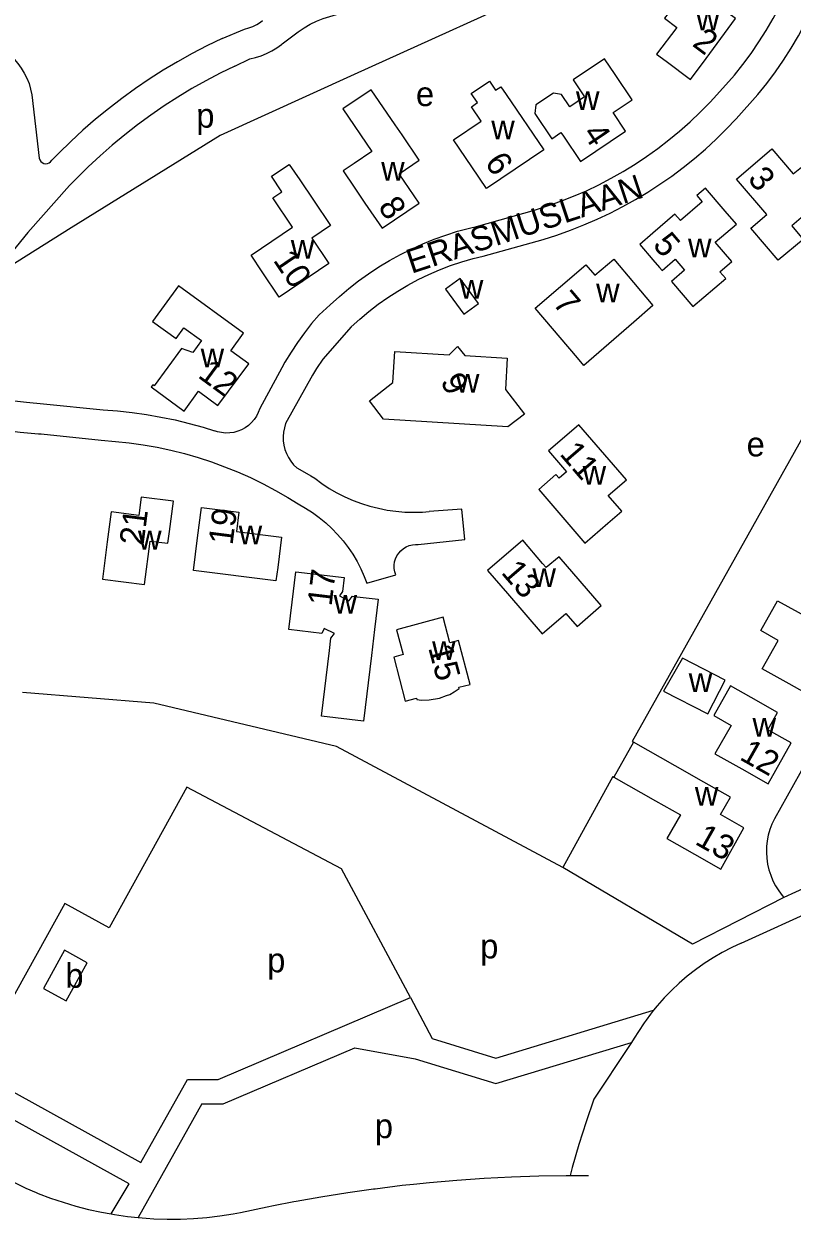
# Model space of a CAD drawing. Extents: x 162804 to 165059, y 381530 to 382901.
# Drawn here: x 163445.8 to 163571.9, y 381530.5 to 381726.8 of the extents above; entities that cross this region are included whole.
import ezdxf

# ---------------------------------------------------------------- set-up
doc = ezdxf.new("R2010")
doc.units = 0
for name, color, linetype in [('BLT_Basislijn', 7, 'Continuous'), ('BLT_Bebouwing', 7, 'Continuous'), ('BLT_Centroide', 7, 'Continuous'), ('BLT_Huisnummer', 7, 'Continuous'), ('BLT_Straatnaam_verkleind', 7, 'Continuous')]:
    doc.layers.add(name, color=color, linetype=linetype)

msp = doc.modelspace()

# ---------------------------------------------------------------- linework, layer by layer
at = {"layer": 'BLT_Basislijn'}
for p, q in [((163478.31, 381724.44), (163481.99, 381725.98)), ((163488.17, 381723.54), (163489.92, 381724.84)), ((163480.43, 381719.91), (163482.9, 381721.07)), ((163559.06, 381714.63), (163562.45, 381718.4)), ((163447.1, 381715.16), (163448.31, 381704.75)), ((163566.31, 381715.22), (163562.74, 381711.25)), ((163600.64, 381707.23), (163545.68, 381608.91)), ((163520.08, 381693.56), (163529.61, 381696.23)), ((163521.2, 381688.68), (163531.02, 381691.43)), ((163496.08, 381680.67), (163494.27, 381679.03)), ((163499.52, 381677.04), (163494.85, 381671.73)), ((163488.12, 381670.33), (163484.5, 381663.62)), ((163493.16, 381669.09), (163488.76, 381661.17)), ((163449.01, 381664.43), (163458.77, 381663.4)), ((163605.92, 381662.34), (163569.01, 381596.23)), ((163448.63, 381659.45), (163458.49, 381658.41)), ((163490.7, 381653.81), (163492.91, 381652.57)), ((163492.91, 381652.57), (163493.53, 381652.17)), ((163502.08, 381634.93), (163506.83, 381636.3)), ((163467.14, 381615.2), (163445.57, 381617)), ((163545.68, 381608.91), (163545.87, 381608.81)), ((163542.48, 381603.17), (163534.27, 381588.25)), ((163542.48, 381603.17), (163542.63, 381603.09)), ((163472.51, 381601.42), (163459.77, 381578.31)), ((163497.94, 381588), (163472.51, 381601.42)), ((163582.56, 381588.85), (163570.59, 381583.31)), ((163509.28, 381566.86), (163497.94, 381588)), ((163563.58, 381575.79), (163584.37, 381585.28)), ((163452.51, 381582.3), (163437.36, 381555.04)), ((163459.77, 381578.31), (163452.51, 381582.3)), ((163477.67, 381553.41), (163509.28, 381566.86)), ((163545.1, 381558.81), (163539.35, 381550.18)), ((163545.56, 381559.5), (163545.1, 381558.81)), ((163546.01, 381560.18), (163545.56, 381559.5)), ((163478.49, 381549.41), (163500.1, 381558.61)), ((163437.36, 381555.04), (163464.99, 381539.75)), ((163464.99, 381539.75), (163472.63, 381553.41)), ((163472.63, 381553.41), (163477.67, 381553.41)), ((163474.98, 381549.41), (163464.53, 381530.72)), ((163474.98, 381549.41), (163478.49, 381549.41))]:
    msp.add_line(p, q, dxfattribs=at)
for points in [[(163538.27, 381743.42), (163534.12, 381734.01), (163500, 381718.5), (163478.02, 381708.51), (163453.55, 381693.34), (163440.16, 381684.96)], [(163562.45, 381718.4), (163563.86, 381720.17), (163565.2, 381721.99), (163566.48, 381723.86), (163567.69, 381725.77), (163568.83, 381727.72), (163569.9, 381729.71), (163570.52, 381730.95)], [(163489.92, 381724.84), (163490.83, 381725.55), (163491.79, 381726.19), (163492.79, 381726.77), (163493.83, 381727.28), (163494.9, 381727.71), (163496, 381728.07), (163497.12, 381728.35), (163498.26, 381728.56), (163499.41, 381728.68), (163499.97, 381728.71)], [(163566.31, 381715.22), (163567.77, 381717.06), (163569.17, 381718.95), (163570.5, 381720.88), (163571.77, 381722.86), (163572.96, 381724.88), (163574.09, 381726.93), (163575.02, 381728.75)], [(163481.99, 381725.98), (163482.69, 381726.16), (163483.37, 381726.4), (163484.01, 381726.72), (163484.62, 381727.11), (163484.97, 381727.38)], [(163478.31, 381724.44), (163475.84, 381723.24), (163473.41, 381721.97), (163471.02, 381720.62), (163468.66, 381719.21), (163466.35, 381717.73), (163464.08, 381716.19), (163461.86, 381714.58), (163459.68, 381712.9), (163457.56, 381711.16), (163455.48, 381709.36), (163453.46, 381707.5), (163451.5, 381705.58), (163450.36, 381704.42)], [(163440.28, 381723.65), (163441.14, 381723.26), (163441.96, 381722.79), (163442.75, 381722.26), (163443.48, 381721.67), (163444.16, 381721.01), (163444.79, 381720.3), (163445.35, 381719.54), (163445.84, 381718.74), (163446.27, 381717.89), (163446.62, 381717.02), (163446.89, 381716.11), (163447.1, 381715.16)], [(163482.9, 381721.07), (163483.83, 381721.28), (163484.75, 381721.57), (163485.63, 381721.94), (163486.49, 381722.38), (163487.3, 381722.88), (163488.07, 381723.46), (163488.17, 381723.54)], [(163480.43, 381719.91), (163478.03, 381718.74), (163475.67, 381717.5), (163473.34, 381716.19), (163471.05, 381714.81), (163468.8, 381713.36), (163466.6, 381711.85), (163464.45, 381710.27), (163462.34, 381708.62), (163460.29, 381706.92), (163458.28, 381705.15), (163456.33, 381703.33), (163454.43, 381701.44), (163453.29, 381700.25)], [(163529.61, 381696.23), (163531.78, 381696.91), (163533.93, 381697.68), (163536.05, 381698.51), (163538.14, 381699.42), (163540.2, 381700.41), (163542.22, 381701.46), (163544.2, 381702.59), (163546.14, 381703.78), (163548.04, 381705.04), (163549.9, 381706.37), (163551.7, 381707.76), (163553.46, 381709.21), (163555.16, 381710.73), (163556.81, 381712.3), (163558.41, 381713.93), (163559.06, 381714.63)], [(163531.02, 381691.43), (163533.28, 381692.14), (163535.51, 381692.93), (163537.72, 381693.79), (163539.89, 381694.73), (163542.03, 381695.73), (163544.14, 381696.81), (163546.2, 381697.96), (163548.23, 381699.18), (163550.22, 381700.47), (163552.16, 381701.83), (163554.05, 381703.24), (163555.89, 381704.73), (163557.69, 381706.27), (163559.43, 381707.87), (163561.11, 381709.53), (163562.74, 381711.25)], [(163448.31, 381704.75), (163448.4, 381704.47), (163448.57, 381704.22), (163448.8, 381704.03), (163449.07, 381703.91), (163449.36, 381703.86), (163449.66, 381703.89), (163449.94, 381704), (163450.17, 381704.18), (163450.36, 381704.42)], [(163453.29, 381700.25), (163446.44, 381692.54), (163440.16, 381684.96)], [(163496.08, 381680.67), (163497.58, 381682.04), (163499.13, 381683.35), (163500.73, 381684.6), (163502.39, 381685.78), (163504.08, 381686.9), (163505.82, 381687.95), (163507.6, 381688.93), (163509.42, 381689.84), (163511.27, 381690.68), (163513.15, 381691.45), (163515.07, 381692.14), (163517, 381692.75), (163518.96, 381693.29), (163520.08, 381693.56)], [(163499.52, 381677.04), (163500.95, 381678.34), (163502.43, 381679.58), (163503.96, 381680.76), (163505.54, 381681.88), (163507.16, 381682.93), (163508.82, 381683.9), (163510.53, 381684.81), (163512.27, 381685.65), (163514.04, 381686.42), (163515.84, 381687.11), (163517.67, 381687.73), (163519.53, 381688.27), (163521.2, 381688.68)], [(163494.27, 381679.03), (163493.02, 381677.58), (163491.83, 381676.07), (163490.7, 381674.51), (163489.64, 381672.91), (163488.65, 381671.27), (163488.12, 381670.33)], [(163494.85, 381671.73), (163493.85, 381670.21), (163493.16, 381669.09)], [(163438.41, 381665.78), (163440.36, 381665.45), (163443.27, 381665.03), (163446.18, 381664.69), (163449.01, 381664.43)], [(163458.77, 381663.4), (163461.16, 381663.23), (163463.54, 381662.98), (163465.91, 381662.65), (163468.27, 381662.24), (163470.61, 381661.76), (163472.94, 381661.19), (163475.24, 381660.55), (163477.07, 381659.98)], [(163484.5, 381663.62), (163484.27, 381662.99), (163483.97, 381662.39), (163483.59, 381661.83), (163483.15, 381661.32), (163482.66, 381660.87), (163482.11, 381660.48), (163481.52, 381660.15), (163480.9, 381659.9), (163480.25, 381659.72), (163479.59, 381659.62), (163478.91, 381659.61), (163478.24, 381659.67), (163477.59, 381659.81), (163477.07, 381659.98)], [(163488.76, 381661.17), (163488.55, 381660.48), (163488.4, 381659.77), (163488.34, 381659.04), (163488.36, 381658.32), (163488.46, 381657.6), (163488.64, 381656.9), (163488.89, 381656.22), (163489.22, 381655.57), (163489.61, 381654.97), (163490.07, 381654.41), (163490.59, 381653.9), (163490.7, 381653.81)], [(163438.36, 381660.72), (163439.24, 381660.56), (163442.21, 381660.12), (163445.19, 381659.77), (163448.18, 381659.48), (163448.63, 381659.45)], [(163458.49, 381658.41), (163460.8, 381658.24), (163463.09, 381658), (163465.38, 381657.67), (163467.65, 381657.27), (163469.91, 381656.79), (163472.15, 381656.23), (163474.37, 381655.59), (163476.57, 381654.87), (163478.74, 381654.08), (163480.88, 381653.22), (163482.99, 381652.28), (163485.06, 381651.27), (163487.1, 381650.18), (163489.1, 381649.03), (163490.83, 381647.96)], [(163493.53, 381652.17), (163494.71, 381651.31), (163495.93, 381650.51), (163497.19, 381649.78), (163498.49, 381649.12), (163499.83, 381648.54), (163501.19, 381648.03), (163502.59, 381647.59), (163504, 381647.24), (163505.43, 381646.96), (163506.87, 381646.75), (163508.33, 381646.63), (163509.78, 381646.59), (163511.24, 381646.63), (163512.31, 381646.71)], [(163490.83, 381647.96), (163492.03, 381647.29), (163493.18, 381646.55), (163494.29, 381645.74), (163495.35, 381644.87), (163496.35, 381643.94), (163497.3, 381642.95), (163498.19, 381641.91), (163499.02, 381640.82), (163499.79, 381639.68), (163500.48, 381638.5), (163501.11, 381637.28), (163501.66, 381636.03), (163502.08, 381634.93)], [(163510.51, 381641.28), (163518.17, 381642.09), (163517.69, 381647.08), (163512.31, 381646.71)], [(163506.83, 381636.3), (163506.67, 381636.82), (163506.58, 381637.35), (163506.57, 381637.89), (163506.64, 381638.42), (163506.8, 381638.94), (163507.02, 381639.43), (163507.32, 381639.88), (163507.67, 381640.28), (163508.09, 381640.62), (163508.55, 381640.9), (163509.05, 381641.11), (163509.57, 381641.24), (163510.1, 381641.3), (163510.51, 381641.28)], [(163534.27, 381588.25), (163497.12, 381608.13), (163467.14, 381615.2)], [(163569.01, 381596.23), (163568.6, 381595.37), (163568.27, 381594.47), (163568.01, 381593.55), (163567.83, 381592.61), (163567.73, 381591.65), (163567.7, 381590.7), (163567.76, 381589.74), (163567.9, 381588.79), (163568.12, 381587.86), (163568.41, 381586.95), (163568.78, 381586.06), (163569.22, 381585.21), (163569.73, 381584.4), (163570.3, 381583.64), (163570.59, 381583.31)], [(163570.59, 381583.31), (163555.58, 381575.61), (163534.27, 381588.25)], [(163563.58, 381575.79), (163562, 381575.06), (163560.45, 381574.26), (163558.95, 381573.38), (163557.49, 381572.44), (163556.07, 381571.44), (163554.7, 381570.36), (163553.38, 381569.23), (163552.11, 381568.04), (163550.9, 381566.79), (163549.75, 381565.49), (163549.19, 381564.79)], [(163509.28, 381566.86), (163512.8, 381560.13), (163523.27, 381556.91), (163549.19, 381564.79)], [(163549.19, 381564.79), (163548.66, 381564.13), (163547.95, 381563.15)], [(163547.95, 381563.15), (163547.64, 381562.73), (163546.68, 381561.28), (163546.01, 381560.18)], [(163500.1, 381558.61), (163510.03, 381556.8), (163523.26, 381552.73), (163545.56, 381559.5)], [(163460.11, 381531.31), (163463.06, 381536.25), (163428.6, 381555.31)], [(163539.35, 381550.18), (163538.1, 381546.46), (163536.93, 381542.72), (163535.83, 381538.96), (163535.46, 381537.62)], [(163509.76, 381536.2), (163512.38, 381536.48), (163516.86, 381536.87), (163521.34, 381537.18), (163525.83, 381537.4), (163530.32, 381537.55), (163534.82, 381537.62), (163535.46, 381537.62)], [(163535.46, 381537.62), (163538.49, 381537.61)], [(163443.49, 381536.83), (163446.12, 381535.53), (163447.77, 381534.83)], [(163490.46, 381533.4), (163494.55, 381534.13), (163498.99, 381534.84), (163503.18, 381535.43)], [(163503.18, 381535.43), (163503.44, 381535.46), (163507.9, 381536.01), (163509.76, 381536.2)], [(163447.77, 381534.83), (163448.12, 381534.68), (163450.15, 381533.91), (163452.21, 381533.22), (163454.3, 381532.6), (163456.4, 381532.06), (163458.52, 381531.59), (163460.11, 381531.31)], [(163486.76, 381532.69), (163490.12, 381533.35), (163490.46, 381533.4)], [(163460.11, 381531.31), (163460.66, 381531.21), (163462.81, 381530.9), (163464.53, 381530.72)], [(163464.53, 381530.72), (163465.85, 381530.62), (163467.14, 381530.53), (163469.31, 381530.46), (163471.48, 381530.47), (163473.65, 381530.57), (163475.82, 381530.74), (163477.98, 381530.99), (163480.13, 381531.32), (163481.32, 381531.54)], [(163481.32, 381531.54), (163485.71, 381532.48), (163486.76, 381532.69)]]:
    msp.add_lwpolyline(points, dxfattribs=at)
at = {"layer": 'BLT_Bebouwing'}
for p, q in [((163524.98, 381715.24), (163531.14, 381706.15)), ((163452.46, 381574.62), (163449, 381568.37))]:
    msp.add_line(p, q, dxfattribs=at)
for points in [[(163557.79, 381721.13), (163562.64, 381727.71), (163555.14, 381733.31), (163552.15, 381729.31), (163550.98, 381727.75), (163552.97, 381726.26), (163549.68, 381721.86), (163551.23, 381720.7), (163555.23, 381717.7), (163557.79, 381721.13)], [(163542.87, 381718.51), (163541.13, 381721.1), (163535.99, 381717.65), (163537.86, 381714.87), (163535.41, 381713.22), (163534.07, 381715.21), (163532.75, 381715.47), (163529.86, 381713.53), (163529.67, 381712.11), (163532.46, 381707.96), (163533.96, 381708.97), (163534.37, 381708.36), (163537.16, 381704.21), (163544.59, 381709.2), (163542.53, 381712.26), (163545.67, 381714.36), (163542.87, 381718.51)], [(163501.79, 381697.39), (163504.59, 381693.24), (163510.66, 381697.36), (163507.38, 381702.2), (163510.67, 381704.44), (163507.87, 381708.58), (163506.73, 381710.26), (163502.82, 381716.02), (163498.17, 381712.86), (163502.91, 381705.88), (163500, 381703.9), (163498.21, 381702.68), (163500, 381700.03), (163501.79, 381697.39)], [(163531.14, 381706.15), (163521.74, 381699.78), (163519.31, 381703.36), (163516.33, 381707.76), (163520.87, 381710.84), (163519.26, 381713.22), (163520.27, 381713.9), (163519.25, 381715.41), (163522.22, 381717.42), (163523.24, 381715.92), (163524.12, 381716.51), (163524.98, 381715.24)], [(163578.11, 381700.63), (163580.09, 381698.34), (163575.34, 381694.27), (163574.18, 381695.63), (163571.87, 381693.64), (163573.76, 381691.43), (163569.63, 381688.03), (163565.16, 381693.25), (163567.78, 381695.49), (163562.79, 381701.3), (163568.6, 381706.28), (163572.12, 381702.17), (163574.84, 381704.41), (163578.11, 381700.63)], [(163493.35, 381697.85), (163496.14, 381693.7), (163493.04, 381691.61), (163495.85, 381687.44), (163487.71, 381681.95), (163484.92, 381686.1), (163483.08, 381688.82), (163489.9, 381693.42), (163486.66, 381698.23), (163488.16, 381699.25), (163486.45, 381701.8), (163489.33, 381703.74), (163491.08, 381701.21), (163493.35, 381697.85)], [(163550.15, 381686.79), (163550.56, 381686.32), (163552.71, 381688.17), (163554.26, 381686.37), (163552.11, 381684.52), (163555.64, 381680.4), (163561.02, 381685.02), (163560.07, 381686.12), (163562.02, 381687.8), (163559.31, 381690.94), (163562.77, 381693.91), (163560.94, 381696.04), (163557.68, 381699.84), (163556.27, 381698.63), (163557.16, 381697.59), (163553.58, 381694.51), (163552.68, 381695.55), (163549.08, 381692.47), (163546.9, 381690.59), (163549.08, 381688.04), (163550.15, 381686.79)], [(163538.07, 381687.27), (163539.55, 381685.53), (163542.63, 381688.15), (163545.87, 381684.35), (163549.08, 381680.58), (163545.93, 381677.82), (163537.75, 381670.73), (163536.71, 381671.94), (163529.71, 381680.14), (163538.07, 381687.27)], [(163471.14, 381683.79), (163466.9, 381677.96), (163470.76, 381675.15), (163472.03, 381676.89), (163474.93, 381674.79), (163473.53, 381672.84), (163471.67, 381673.48), (163467.18, 381667.37), (163466.93, 381667.55), (163466.66, 381667.18), (163472.07, 381663.2), (163474.47, 381666.47), (163477.63, 381664.15), (163482.71, 381670.97), (163479.74, 381673.13), (163481.83, 381676.01), (163471.14, 381683.79)], [(163541.67, 381644.8), (163543.96, 381646.77), (163541.74, 381649.36), (163544.71, 381651.92), (163536.93, 381660.97), (163535.71, 381659.92), (163531.92, 381656.66), (163534.88, 381653.21), (163533.66, 381652.17), (163533.14, 381652.78), (163530.31, 381650.34), (163537.88, 381641.54), (163541.67, 381644.8)], [(163469.7, 381643.44), (163470.33, 381648.39), (163465.04, 381649.07), (163464.66, 381646.08), (163460.11, 381646.66), (163459.47, 381641.71), (163458.68, 381635.59), (163465.57, 381634.7), (163466.49, 381641.86), (163469.44, 381641.49), (163469.7, 381643.44)], [(163487.45, 381637.53), (163487.17, 381635.31), (163473.61, 381637.05), (163474.3, 381642.41), (163474.94, 381647.37), (163481.09, 381646.58), (163480.69, 381643.44), (163488.09, 381642.49), (163487.45, 381637.53)], [(163530.96, 381638.2), (163527.7, 381641.99), (163521.92, 381637.02), (163525.18, 381633.23), (163530.87, 381626.6), (163534.79, 381629.97), (163536.61, 381627.84), (163540.57, 381631.25), (163533.65, 381639.29), (163531.56, 381637.49), (163530.96, 381638.2)], [(163500, 381632.77), (163503.95, 381632.31), (163503.36, 381627.35), (163502.85, 381623.07), (163501.55, 381612.27), (163494.67, 381613.09), (163495.95, 381623.89), (163496.19, 381625.89), (163496.77, 381626.67), (163495.08, 381627.5), (163494.72, 381626.67), (163489.28, 381627.32), (163489.82, 381631.83), (163490.41, 381636.79), (163498.39, 381635.85), (163498.12, 381633.6), (163497.58, 381632.87), (163499.16, 381632.02), (163499.74, 381632.8), (163500, 381632.77)], [(163572.94, 381630.16), (163577.3, 381627.72), (163575.7, 381624.86), (163579.57, 381622.69), (163575.83, 381615.95), (163571.46, 381618.38), (163567.02, 381620.86), (163569.64, 381625.54), (163566.78, 381627.14), (163569.53, 381632.06), (163572.94, 381630.16)], [(163514.6, 381629.34), (163506.98, 381627.29), (163508.08, 381623.2), (163506.55, 381622.8), (163508.4, 381615.58), (163510.24, 381616.05), (163510.29, 381615.85), (163511.08, 381615.71), (163512.35, 381615.77), (163514.04, 381616.06), (163515.17, 381616.46), (163515.72, 381616.65), (163516.41, 381617.08), (163517.27, 381617.64), (163517.22, 381617.83), (163519.06, 381618.3), (163517.12, 381625.53), (163515.73, 381625.15), (163514.6, 381629.34)], [(163565.19, 381616.15), (163561.83, 381618.06), (163559.07, 381613.18), (163561.9, 381611.58), (163559.26, 381606.91), (163563.65, 381604.42), (163568, 381601.96), (163571.77, 381608.69), (163567.94, 381610.86), (163569.55, 381613.69), (163565.19, 381616.15)], [(163545.87, 381608.81), (163542.63, 381603.09)], [(163552.74, 381604.92), (163545.87, 381608.81)], [(163557.44, 381602.26), (163552.74, 381604.92)], [(163542.63, 381603.09), (163549.51, 381599.2)], [(163549.51, 381599.2), (163553.6, 381596.88), (163551.38, 381592.97), (163555.87, 381590.43), (163560.23, 381587.97), (163563.99, 381594.77), (163560.16, 381596.93), (163561.79, 381599.8), (163557.44, 381602.26)], [(163449, 381568.37), (163452.72, 381566.31), (163456.18, 381572.57), (163452.46, 381574.62)]]:
    msp.add_lwpolyline(points, dxfattribs=at)
for points in [[(163517.43, 381685.02), (163515.03, 381683.27), (163518.03, 381679.15), (163520.43, 381680.9)], [(163506.7, 381673.03), (163515.63, 381672.48), (163516.99, 381673.85), (163518.18, 381672.32), (163525.16, 381671.89), (163524.85, 381666.75), (163527.97, 381662.72), (163525.26, 381660.61), (163504.85, 381661.87), (163502.51, 381664.88), (163506.38, 381667.89)], [(163553.91, 381622.61), (163550.81, 381617.19), (163558.08, 381613.45), (163560.93, 381618.99)]]:
    msp.add_lwpolyline(points, close=True, dxfattribs=at)

# ---------------------------------------------------------------- texts
at = {"layer": 'BLT_Centroide'}
for s, p in [('w', (163556.16, 381725.75)), ('e', (163510.16, 381713.32)), ('w', (163536.43, 381712.66)), ('p', (163474.09, 381709.78)), ('w', (163522.52, 381707.88)), ('w', (163504.44, 381701.09)), ('w', (163489.61, 381688.23)), ('w', (163554.83, 381688.47)), ('w', (163517.36, 381681.67)), ('w', (163539.74, 381681.09)), ('w', (163474.8, 381670.42)), ('w', (163516.72, 381666.25)), ('e', (163564.46, 381655.77)), ('w', (163537.52, 381651.12)), ('w', (163464.52, 381640.47)), ('w', (163481.05, 381641.34)), ('w', (163529.28, 381634.3)), ('w', (163496.63, 381629.94)), ('w', (163512.8, 381622.34)), ('w', (163554.95, 381617.04)), ('w', (163565.42, 381609.72)), ('w', (163555.96, 381598.38)), ('p', (163520.71, 381573.29)), ('b', (163452.59, 381568.47)), ('p', (163485.73, 381571.01)), ('p', (163503.41, 381543.76))]:
    msp.add_text(s, height=4, dxfattribs=at).set_placement(p)
at = {"layer": 'BLT_Huisnummer'}
for s, rotation, p in [('2', 323.2126, (163555.37, 381723.32)), ('4', 303.9284, (163537.42, 381708.83)), ('6', 304.1473, (163521.35, 381704.04)), ('3', 310.6361, (163564.48, 381701.28)), ('8', 304.0269, (163503.83, 381696.78)), ('5', 310.6353, (163548.9, 381690.44)), ('10', 303.9761, (163486.61, 381688)), ('7', 310.4635, (163532.48, 381680.86)), ('12', 323.6984, (163474.18, 381668.85)), ('9', 299.3373, (163514.07, 381668.09)), ('11', 310.6901, (163533.62, 381656.12)), ('21', 82.6712, (163465.4, 381640.97)), ('19', 82.6902, (163480.03, 381641.09)), ('13', 310.6933, (163524.02, 381636.64)), ('17', 83.1536, (163496.29, 381631.06)), ('15', 285.0324, (163512.15, 381624.34)), ('12', 330.4962, (163563.12, 381606.06)), ('13', 330.5068, (163555.8, 381592.16))]:
    msp.add_text(s, height=4, rotation=rotation, dxfattribs=at).set_placement(p)
at = {"layer": 'BLT_Straatnaam_verkleind'}
msp.add_text('ERASMUSLAAN', height=3.9999, rotation=18.231, dxfattribs=at).set_placement((163509.41, 381685.75))

doc.saveas('drawing.dxf')
